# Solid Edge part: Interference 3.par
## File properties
Last saved by: Lee
Revision: 59
Accuracy: 0.990
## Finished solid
Body 1: solid body, 4 faces, 4 edges, 0 vertices.
  Faces by surface: cylinder 4
  Edges by curve: intersection 4
Bounding box of the edges (mm): 98.450 x 219.080 x 337.967, from (813.0361, 155.4642, 258.3711) to (911.4856, 374.5444, 596.3379).
Cylindrical faces by radius (mm): R91 x1, R109.5375 x1, R850 x1, R875.4 x1
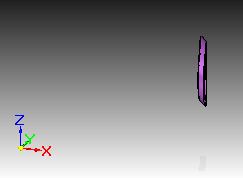
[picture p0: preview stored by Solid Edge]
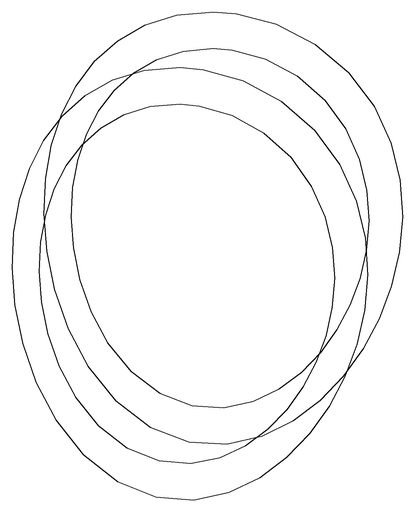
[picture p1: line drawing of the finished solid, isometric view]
